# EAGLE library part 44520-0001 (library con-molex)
STACKED MODULAR JACK CATEGORY 5 Source: http://www.molex.com/pdm_docs/sd/445200006_sd.pdf
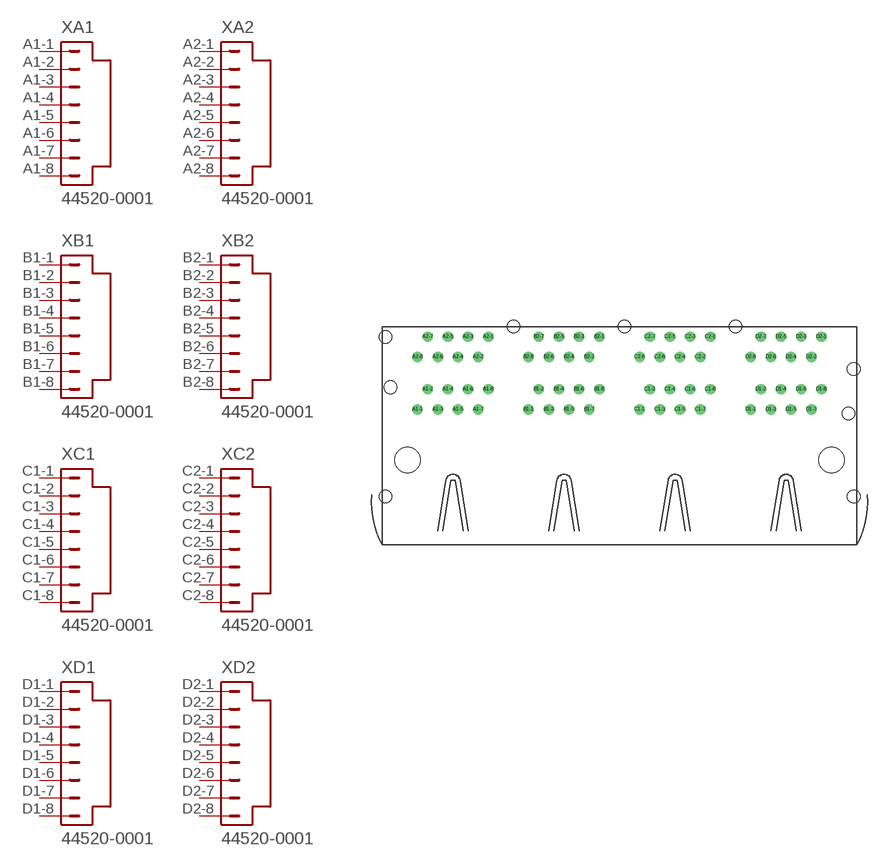
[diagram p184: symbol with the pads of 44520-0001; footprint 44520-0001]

Designator prefix X; gates A1=CON-1X8 A2=CON-1X8 B1=CON-1X8 B2=CON-1X8 C1=CON-1X8 C2=CON-1X8 D1=CON-1X8 D2=CON-1X8

## 44520-0001 (MPN: 44520-0001; OC_FARNELL: unknown; OC_NEWARK: 92C1819)  [44520-0001]
A1-1  A1:1  pas
A1-2  A1:2  pas
A1-3  A1:3  pas
A1-4  A1:4  pas
A1-5  A1:5  pas
A1-6  A1:6  pas
A1-7  A1:7  pas
A1-8  A1:8  pas
A2-1  A2:1  pas
A2-2  A2:2  pas
A2-3  A2:3  pas
A2-4  A2:4  pas
A2-5  A2:5  pas
A2-6  A2:6  pas
A2-7  A2:7  pas
A2-8  A2:8  pas
B1-1  B1:1  pas
B1-2  B1:2  pas
B1-3  B1:3  pas
B1-4  B1:4  pas
B1-5  B1:5  pas
B1-6  B1:6  pas
B1-7  B1:7  pas
B1-8  B1:8  pas
B2-1  B2:1  pas
B2-2  B2:2  pas
B2-3  B2:3  pas
B2-4  B2:4  pas
B2-5  B2:5  pas
B2-6  B2:6  pas
B2-7  B2:7  pas
B2-8  B2:8  pas
C1-1  C1:1  pas
C1-2  C1:2  pas
C1-3  C1:3  pas
C1-4  C1:4  pas
C1-5  C1:5  pas
C1-6  C1:6  pas
C1-7  C1:7  pas
C1-8  C1:8  pas
C2-1  C2:1  pas
C2-2  C2:2  pas
C2-3  C2:3  pas
C2-4  C2:4  pas
C2-5  C2:5  pas
C2-6  C2:6  pas
C2-7  C2:7  pas
C2-8  C2:8  pas
D1-1  D1:1  pas
D1-2  D1:2  pas
D1-3  D1:3  pas
D1-4  D1:4  pas
D1-5  D1:5  pas
D1-6  D1:6  pas
D1-7  D1:7  pas
D1-8  D1:8  pas
D2-1  D2:1  pas
D2-2  D2:2  pas
D2-3  D2:3  pas
D2-4  D2:4  pas
D2-5  D2:5  pas
D2-6  D2:6  pas
D2-7  D2:7  pas
D2-8  D2:8  pas

## Footprint 44520-0001 (pad centres in mm)
STACKED MODULAR JACK CATEGORY 5 Source: http://www.molex.com/pdm_docs/sd/445200006_sd.pdf
drill 0.8 round: A1-1 -25.4,6.35; A1-2 -24.13,8.89; A1-3 -22.86,6.35; A1-4 -21.59,8.89; A1-5 -20.32,6.35; A1-6 -19.05,8.89; A1-7 -17.78,6.35; A1-8 -16.51,8.89; A2-1 -16.51,15.494; A2-2 -17.78,12.954; A2-3 -19.05,15.494; A2-4 -20.32,12.954; A2-5 -21.59,15.494; A2-6 -22.86,12.954; A2-7 -24.13,15.494; A2-8 -25.4,12.954; B1-1 -11.43,6.35; B1-2 -10.16,8.89; B1-3 -8.89,6.35; B1-4 -7.62,8.89; B1-5 -6.35,6.35; B1-6 -5.08,8.89; B1-7 -3.81,6.35; B1-8 -2.54,8.89; B2-1 -2.54,15.494; B2-2 -3.81,12.954; B2-3 -5.08,15.494; B2-4 -6.35,12.954; B2-5 -7.62,15.494; B2-6 -8.89,12.954; B2-7 -10.16,15.494; B2-8 -11.43,12.954; C1-1 2.54,6.35; C1-2 3.81,8.89; C1-3 5.08,6.35; C1-4 6.35,8.89; C1-5 7.62,6.35; C1-6 8.89,8.89; C1-7 10.16,6.35; C1-8 11.43,8.89; C2-1 11.43,15.494; C2-2 10.16,12.954; C2-3 8.89,15.494; C2-4 7.62,12.954; C2-5 6.35,15.494; C2-6 5.08,12.954; C2-7 3.81,15.494; C2-8 2.54,12.954; D1-1 16.51,6.35; D1-2 17.78,8.89; D1-3 19.05,6.35; D1-4 20.32,8.89; D1-5 21.59,6.35; D1-6 22.86,8.89; D1-7 24.13,6.35; D1-8 25.4,8.89; D2-1 25.4,15.494; D2-2 24.13,12.954; D2-3 22.86,15.494; D2-4 21.59,12.954; D2-5 20.32,15.494; D2-6 19.05,12.954; D2-7 17.78,15.494; D2-8 16.51,12.954
hole 1.575 at 29.464,-4.572
hole 3.251 at 26.67,0
hole 1.575 at -28.829,9.144
hole 1.575 at -29.464,15.494
hole 1.575 at -13.335,16.764
hole 1.575 at 14.605,16.764
hole 1.575 at 0.635,16.764
hole 1.575 at 28.829,5.842
hole 1.575 at 29.464,11.43
hole 3.251 at -26.67,0
hole 1.575 at -29.464,-4.572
